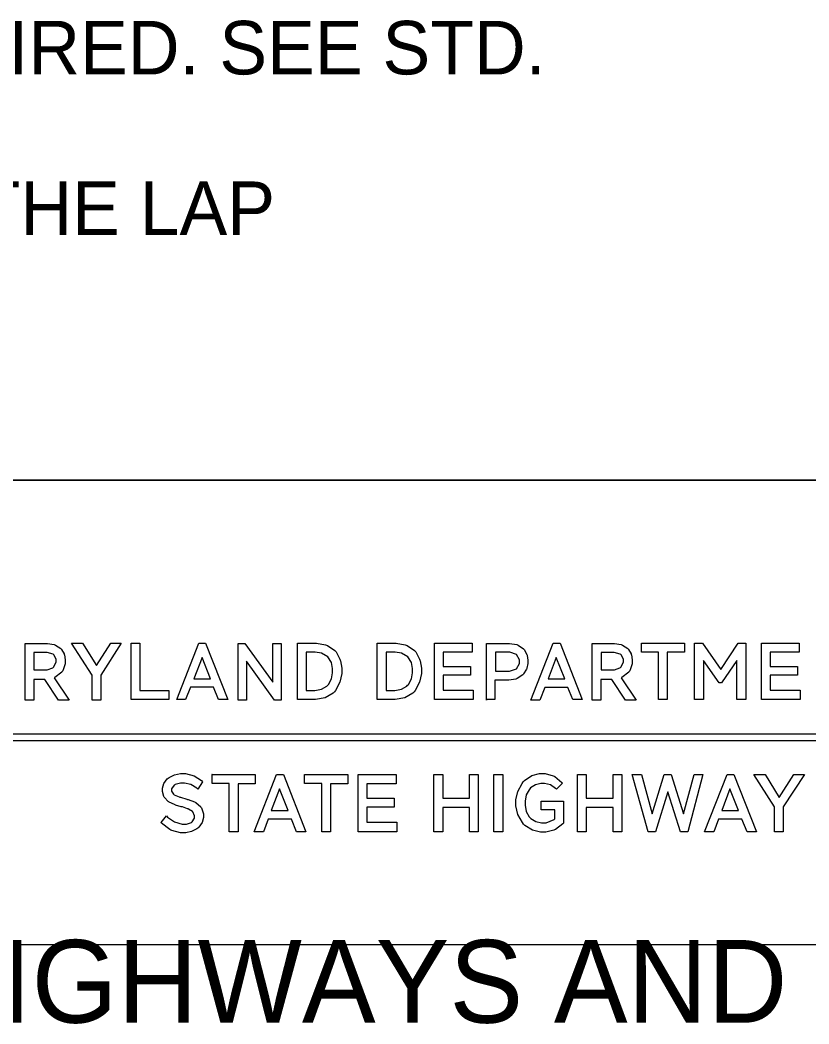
# Model space of a CAD drawing. Extents: x -53.2 to -44.7, y -19.5 to -8.5.
# Drawn here: x -47.919 to -47.035, y -18.391 to -17.266 of the extents above; entities that cross this region are included whole.
import ezdxf

# ---------------------------------------------------------------- set-up
doc = ezdxf.new("R2010")
doc.units = 0
for name, color, linetype in [('BORD-LINE', 7, 'Continuous'), ('Level 13', 7, 'Continuous'), ('MSHA-LOGO', 7, 'Continuous'), ('TTLB-TEXT', 7, 'Continuous'), ('USER-LINE', 7, 'Continuous')]:
    doc.layers.add(name, color=color, linetype=linetype)

msp = doc.modelspace()

# ---------------------------------------------------------------- linework, layer by layer
at = {"layer": 'BORD-LINE'}
msp.add_line((-45.0478, -17.7814), (-49.5207, -17.7814), dxfattribs=at)
at = {"layer": 'MSHA-LOGO'}
for points in [[(-47.9133, -18.0277), (-47.9133, -17.9642), (-47.891, -17.9642), (-47.8882, -17.9642), (-47.8807, -17.9656), (-47.8799, -17.9658), (-47.8791, -17.9661), (-47.8734, -17.9699), (-47.873, -17.9704), (-47.8726, -17.9709), (-47.8697, -17.9761), (-47.8694, -17.9767), (-47.8693, -17.9772), (-47.8684, -17.9825), (-47.8684, -17.9842), (-47.8684, -17.9871), (-47.8711, -17.9949), (-47.8717, -17.9957), (-47.8723, -17.9966), (-47.8799, -18.0023), (-47.8809, -18.0027), (-47.8638, -18.028), (-47.8759, -18.028), (-47.8913, -18.0046), (-47.9034, -18.0046), (-47.9034, -18.028), (-47.9133, -18.028)], [(-47.8285, -18), (-47.8285, -18.0277), (-47.8383, -18.0277), (-47.8383, -18), (-47.8612, -17.9638), (-47.8491, -17.9638), (-47.8334, -17.9892), (-47.8174, -17.9638), (-47.8056, -17.9638)], [(-47.7945, -17.9638), (-47.7846, -17.9638), (-47.7846, -18.0171), (-47.7522, -18.0171), (-47.7522, -18.0273), (-47.7945, -18.0273)], [(-47.7185, -17.9638), (-47.711, -17.9638), (-47.6861, -18.0273), (-47.6966, -18.0273), (-47.7022, -18.0132), (-47.728, -18.0132), (-47.7336, -18.0273), (-47.7434, -18.0273)], [(-47.6338, -18.0277), (-47.6652, -17.9842), (-47.6652, -18.0277), (-47.6747, -18.0277), (-47.6747, -17.9642), (-47.6672, -17.9642), (-47.6357, -18.0076), (-47.6357, -17.9642), (-47.6262, -17.9642), (-47.6262, -18.0277)], [(-47.6082, -17.9638), (-47.5906, -17.9638), (-47.5868, -17.9638), (-47.5766, -17.9657), (-47.5755, -17.9661), (-47.5745, -17.9666), (-47.5661, -17.9723), (-47.5654, -17.973), (-47.5648, -17.9738), (-47.5604, -17.982), (-47.5602, -17.9829), (-47.5599, -17.9838), (-47.5585, -17.992), (-47.5585, -17.9948), (-47.5585, -17.998), (-47.5605, -18.0078), (-47.5653, -18.0169), (-47.5667, -18.0184), (-47.5681, -18.0199), (-47.577, -18.0251), (-47.5879, -18.0273), (-47.5916, -18.0273), (-47.6082, -18.0273)], [(-47.5189, -17.9638), (-47.5012, -17.9638), (-47.4975, -17.9638), (-47.4873, -17.9657), (-47.4862, -17.9661), (-47.4851, -17.9666), (-47.4767, -17.9723), (-47.4761, -17.973), (-47.4755, -17.9738), (-47.4711, -17.982), (-47.4708, -17.9829), (-47.4706, -17.9838), (-47.4692, -17.992), (-47.4692, -17.9948), (-47.4692, -17.998), (-47.4712, -18.0078), (-47.476, -18.0169), (-47.4773, -18.0184), (-47.4787, -18.0199), (-47.4877, -18.0251), (-47.4986, -18.0273), (-47.5022, -18.0273), (-47.5189, -18.0273)], [(-47.4544, -17.9638), (-47.4122, -17.9638), (-47.4122, -17.974), (-47.4446, -17.974), (-47.4446, -17.9902), (-47.4142, -17.9902), (-47.4142, -18), (-47.4446, -18), (-47.4446, -18.0168), (-47.4113, -18.0168), (-47.4113, -18.027), (-47.4544, -18.027)], [(-47.3962, -18.0277), (-47.3962, -17.9642), (-47.3733, -17.9642), (-47.3704, -17.9642), (-47.3623, -17.9656), (-47.3615, -17.9658), (-47.3607, -17.9661), (-47.3547, -17.9703), (-47.3543, -17.9707), (-47.3539, -17.9712), (-47.3509, -17.9767), (-47.3507, -17.9773), (-47.3506, -17.9779), (-47.3497, -17.9831), (-47.3497, -17.9849), (-47.3497, -17.9868), (-47.3508, -17.9919), (-47.351, -17.9925), (-47.3513, -17.993), (-47.3546, -17.9985), (-47.355, -17.999), (-47.3554, -17.9995), (-47.3617, -18.0036), (-47.3625, -18.004), (-47.3633, -18.0043), (-47.371, -18.0056), (-47.3736, -18.0056), (-47.3867, -18.0056), (-47.3867, -18.0273), (-47.3962, -18.0273)], [(-47.3213, -17.9638), (-47.3137, -17.9638), (-47.2889, -18.0273), (-47.2993, -18.0273), (-47.3049, -18.0135), (-47.3308, -18.0135), (-47.3363, -18.0277), (-47.3464, -18.0277)], [(-47.2777, -18.0277), (-47.2777, -17.9642), (-47.2555, -17.9642), (-47.2527, -17.9642), (-47.2452, -17.9656), (-47.2444, -17.9658), (-47.2436, -17.9661), (-47.2379, -17.9699), (-47.2375, -17.9704), (-47.2371, -17.9709), (-47.2341, -17.9761), (-47.2339, -17.9767), (-47.2337, -17.9772), (-47.2329, -17.9825), (-47.2329, -17.9842), (-47.2329, -17.9871), (-47.2356, -17.9949), (-47.2362, -17.9957), (-47.2368, -17.9966), (-47.2444, -18.0023), (-47.2453, -18.0027), (-47.2283, -18.028), (-47.2404, -18.028), (-47.2558, -18.0046), (-47.2679, -18.0046), (-47.2679, -18.028), (-47.2777, -18.028)], [(-47.2224, -17.9638), (-47.1743, -17.9638), (-47.1743, -17.974), (-47.1936, -17.974), (-47.1936, -18.0273), (-47.2034, -18.0273), (-47.2034, -17.974), (-47.2224, -17.974)], [(-47.1629, -17.9638), (-47.154, -17.9638), (-47.1337, -17.9935), (-47.1141, -17.9638), (-47.1056, -17.9638), (-47.1056, -18.0273), (-47.1154, -18.0273), (-47.1154, -17.9833), (-47.1328, -18.0086), (-47.1354, -18.0086), (-47.153, -17.9833), (-47.153, -18.0273), (-47.1629, -18.0273)], [(-47.0879, -17.9638), (-47.0457, -17.9638), (-47.0457, -17.974), (-47.0781, -17.974), (-47.0781, -17.9902), (-47.0477, -17.9902), (-47.0477, -18), (-47.0781, -18), (-47.0781, -18.0168), (-47.0447, -18.0168), (-47.0447, -18.027), (-47.0879, -18.027)], [(-47.9034, -17.9744), (-47.9034, -17.9938), (-47.8907, -17.9938), (-47.8885, -17.9938), (-47.8824, -17.9915), (-47.8818, -17.9911), (-47.8814, -17.9907), (-47.8786, -17.9854), (-47.8786, -17.9836), (-47.8786, -17.9819), (-47.881, -17.9771), (-47.8815, -17.9767), (-47.882, -17.9763), (-47.8887, -17.9744), (-47.891, -17.9744)], [(-47.7241, -18.004), (-47.7055, -18.004), (-47.7149, -17.98)], [(-47.5984, -17.9744), (-47.5984, -18.0171), (-47.5909, -18.0171), (-47.5885, -18.0171), (-47.5811, -18.0156), (-47.5751, -18.0122), (-47.5742, -18.0112), (-47.5733, -18.0102), (-47.5701, -18.0041), (-47.5687, -17.9971), (-47.5687, -17.9948), (-47.5687, -17.9925), (-47.57, -17.9857), (-47.5741, -17.9792), (-47.581, -17.9753), (-47.5882, -17.974), (-47.5906, -17.974), (-47.5984, -17.974)], [(-47.5088, -17.9744), (-47.5088, -18.0171), (-47.5012, -18.0171), (-47.4988, -18.0171), (-47.4914, -18.0156), (-47.4855, -18.0122), (-47.4846, -18.0112), (-47.4837, -18.0102), (-47.4804, -18.0041), (-47.479, -17.9971), (-47.479, -17.9948), (-47.479, -17.9925), (-47.4804, -17.9857), (-47.4844, -17.9792), (-47.4913, -17.9753), (-47.4985, -17.974), (-47.5009, -17.974), (-47.5088, -17.974)], [(-47.3861, -17.974), (-47.3861, -17.9954), (-47.373, -17.9954), (-47.3704, -17.9954), (-47.3627, -17.9927), (-47.3592, -17.9866), (-47.3592, -17.9846), (-47.3592, -17.9826), (-47.3625, -17.9767), (-47.3699, -17.974), (-47.3723, -17.974)], [(-47.3272, -18.004), (-47.3085, -18.004), (-47.318, -17.98)], [(-47.2676, -17.9744), (-47.2676, -17.9938), (-47.2548, -17.9938), (-47.2526, -17.9938), (-47.2466, -17.9915), (-47.246, -17.9911), (-47.2455, -17.9907), (-47.2427, -17.9854), (-47.2427, -17.9836), (-47.2427, -17.9819), (-47.2452, -17.9771), (-47.2457, -17.9767), (-47.2462, -17.9763), (-47.2529, -17.9744), (-47.2552, -17.9744)], [(-48.0516, -18.0656), (-45.935, -18.0656), (-45.935, -18.0735), (-48.0516, -18.0735)], [(-47.7255, -18.1529), (-47.7259, -18.1526), (-47.7301, -18.1499), (-47.7306, -18.1497), (-47.7312, -18.1495), (-47.7371, -18.1476), (-47.7377, -18.1474), (-47.7383, -18.1473), (-47.7447, -18.1454), (-47.7453, -18.1452), (-47.746, -18.1449), (-47.7518, -18.1423), (-47.7524, -18.142), (-47.7529, -18.1416), (-47.7572, -18.137), (-47.7575, -18.1365), (-47.7578, -18.1359), (-47.7594, -18.1301), (-47.7594, -18.1282), (-47.7594, -18.1264), (-47.7578, -18.1211), (-47.7541, -18.1162), (-47.753, -18.1153), (-47.752, -18.1144), (-47.7458, -18.1114), (-47.739, -18.1102), (-47.7367, -18.1102), (-47.7335, -18.1102), (-47.724, -18.1125), (-47.7157, -18.1179), (-47.7144, -18.1195), (-47.7198, -18.1275), (-47.721, -18.1264), (-47.7277, -18.1224), (-47.7347, -18.1208), (-47.737, -18.1208), (-47.7392, -18.1208), (-47.7451, -18.1224), (-47.7457, -18.1227), (-47.7462, -18.123), (-47.7492, -18.1271), (-47.7492, -18.1285), (-47.7492, -18.1298), (-47.747, -18.1332), (-47.7466, -18.1336), (-47.7462, -18.1339), (-47.7406, -18.1363), (-47.7399, -18.1365), (-47.7392, -18.1366), (-47.7321, -18.1388), (-47.7313, -18.1391), (-47.7305, -18.1393), (-47.7233, -18.142), (-47.7227, -18.1423), (-47.722, -18.1426), (-47.7164, -18.1474), (-47.716, -18.1481), (-47.7156, -18.1487), (-47.7134, -18.1552), (-47.7134, -18.1574), (-47.7134, -18.1593), (-47.715, -18.165), (-47.7187, -18.1703), (-47.7198, -18.1712), (-47.7208, -18.1721), (-47.7269, -18.1752), (-47.7333, -18.1766), (-47.7354, -18.1766), (-47.7391, -18.1766), (-47.7489, -18.174), (-47.7501, -18.1734), (-47.7513, -18.1729), (-47.7604, -18.1659), (-47.761, -18.1651), (-47.7549, -18.1574), (-47.7537, -18.1589), (-47.746, -18.1643), (-47.7374, -18.1667), (-47.7345, -18.1667), (-47.7325, -18.1667), (-47.727, -18.1651), (-47.7265, -18.1648), (-47.726, -18.1644), (-47.7236, -18.1603), (-47.7236, -18.159), (-47.7236, -18.1575), (-47.7252, -18.1532)], [(-47.7041, -18.1111), (-47.6556, -18.1111), (-47.6556, -18.1217), (-47.6747, -18.1217), (-47.6747, -18.1754), (-47.6846, -18.1754), (-47.6846, -18.1214), (-47.7038, -18.1214), (-47.7038, -18.1111)], [(-47.6316, -18.1111), (-47.6239, -18.1111), (-47.5987, -18.1754), (-47.6092, -18.1754), (-47.6147, -18.1612), (-47.6409, -18.1612), (-47.6463, -18.1754), (-47.6565, -18.1754)], [(-47.6003, -18.1111), (-47.5517, -18.1111), (-47.5517, -18.1217), (-47.5709, -18.1217), (-47.5709, -18.1754), (-47.5808, -18.1754), (-47.5808, -18.1214), (-47.6, -18.1214), (-47.6, -18.1111)], [(-47.5402, -18.1111), (-47.4974, -18.1111), (-47.4974, -18.1217), (-47.5303, -18.1217), (-47.5303, -18.1378), (-47.4997, -18.1378), (-47.4997, -18.1477), (-47.5303, -18.1477), (-47.5303, -18.1648), (-47.4968, -18.1648), (-47.4968, -18.1754), (-47.5402, -18.1754)], [(-47.4153, -18.1481), (-47.4453, -18.1481), (-47.4453, -18.1754), (-47.4552, -18.1754), (-47.4552, -18.1111), (-47.4453, -18.1111), (-47.4453, -18.1378), (-47.4153, -18.1378), (-47.4153, -18.1111), (-47.4054, -18.1111), (-47.4054, -18.1754), (-47.4153, -18.1754)], [(-47.3878, -18.1111), (-47.3779, -18.1111), (-47.3779, -18.1754), (-47.3878, -18.1754)], [(-47.3348, -18.141), (-47.3099, -18.141), (-47.3099, -18.1657), (-47.3105, -18.1665), (-47.3188, -18.1727), (-47.3198, -18.1731), (-47.3208, -18.1736), (-47.3296, -18.1757), (-47.3325, -18.1757), (-47.3356, -18.1757), (-47.3448, -18.1735), (-47.3532, -18.1682), (-47.3546, -18.1667), (-47.356, -18.1651), (-47.3611, -18.1562), (-47.3632, -18.1462), (-47.3632, -18.1429), (-47.3632, -18.1397), (-47.3611, -18.1301), (-47.3563, -18.1211), (-47.3549, -18.1195), (-47.3535, -18.1179), (-47.3453, -18.1124), (-47.3367, -18.1102), (-47.3338, -18.1102), (-47.3305, -18.1102), (-47.3214, -18.1126), (-47.3204, -18.1131), (-47.3194, -18.1135), (-47.3117, -18.12), (-47.3111, -18.1208), (-47.3178, -18.1278), (-47.3187, -18.1267), (-47.3243, -18.1228), (-47.331, -18.1211), (-47.3332, -18.1211), (-47.3352, -18.1211), (-47.3413, -18.1226), (-47.3467, -18.1261), (-47.3475, -18.1272), (-47.3484, -18.1282), (-47.3516, -18.1341), (-47.353, -18.141), (-47.353, -18.1433), (-47.353, -18.1456), (-47.3516, -18.1525), (-47.3482, -18.1586), (-47.3472, -18.1596), (-47.3463, -18.1606), (-47.3407, -18.1639), (-47.3346, -18.1654), (-47.3325, -18.1654), (-47.3293, -18.1654), (-47.3203, -18.1616), (-47.3194, -18.1609), (-47.3194, -18.1509), (-47.3348, -18.1509)], [(-47.2543, -18.1481), (-47.2843, -18.1481), (-47.2843, -18.1754), (-47.2942, -18.1754), (-47.2942, -18.1111), (-47.2843, -18.1111), (-47.2843, -18.1378), (-47.2543, -18.1378), (-47.2543, -18.1111), (-47.2444, -18.1111), (-47.2444, -18.1754), (-47.2543, -18.1754)], [(-47.1706, -18.1754), (-47.1789, -18.1754), (-47.1929, -18.1307), (-47.2067, -18.1754), (-47.215, -18.1754), (-47.2329, -18.1111), (-47.2226, -18.1111), (-47.2105, -18.1554), (-47.1971, -18.1111), (-47.1891, -18.1111), (-47.1753, -18.1554), (-47.1635, -18.1111), (-47.1536, -18.1111)], [(-47.1265, -18.1111), (-47.1188, -18.1111), (-47.0935, -18.1754), (-47.1041, -18.1754), (-47.1098, -18.1612), (-47.136, -18.1612), (-47.1415, -18.1754), (-47.1517, -18.1754)], [(-47.0635, -18.1474), (-47.0635, -18.1754), (-47.0734, -18.1754), (-47.0734, -18.1474), (-47.0964, -18.1111), (-47.084, -18.1111), (-47.068, -18.1368), (-47.0517, -18.1111), (-47.0399, -18.1111)], [(-47.6374, -18.1516), (-47.6185, -18.1516), (-47.6281, -18.1272)], [(-47.1325, -18.1516), (-47.1137, -18.1516), (-47.1233, -18.1272)]]:
    msp.add_lwpolyline(points, close=True, dxfattribs=at)
at = {"layer": 'USER-LINE'}
msp.add_lwpolyline([(-45.7987, -18.3022), (-48.7699, -18.3022), (-48.7699, -17.7814), (-45.7987, -17.7814)], close=True, dxfattribs=at)

# ---------------------------------------------------------------- texts
at = {"layer": 'Level 13'}
for s, height, p in [('WHEN THE BARRIER IS CONSTRUCTED USING THE SLIP FORM METHOD, DIAGONAL NO. 4 BARS ARE REQUIRED. SEE STD. ', 0.0600095, (-52.132, -17.3265)), ('THE CONTRACTOR MAY CONSTRUCT THE VERTICAL NO. 5 BARS AS SHOWN ON THIS STANDARD OR USE THE LAP', 0.06001, (-52.132, -17.5065))]:
    msp.add_text(s, height=height, dxfattribs=at).set_placement(p)
at = {"layer": 'TTLB-TEXT'}
msp.add_text('STANDARDS FOR HIGHWAYS AND INCIDENTAL STRUCTURES', height=0.09269, dxfattribs=at).set_placement((-49.1249, -18.3894))

doc.saveas('drawing.dxf')
